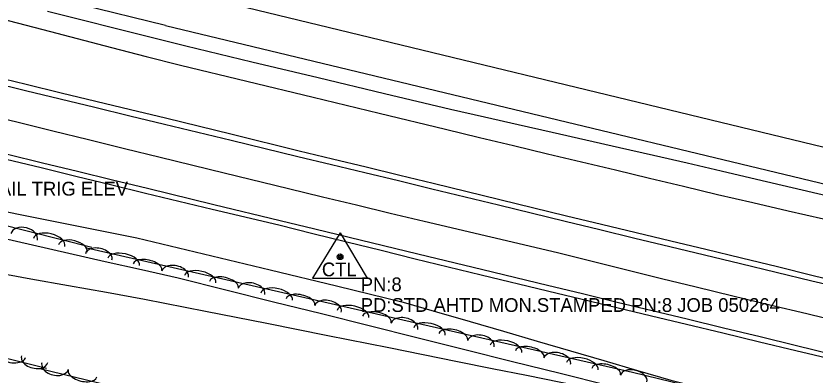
# Model space of a CAD drawing. Extents: x 1441650 to 1491889, y 345904 to 358319.
# Drawn here: x 1449187.5 to 1449477.3, y 353638.8 to 353769 of the extents above; entities that cross this region are included whole.
import ezdxf

# ---------------------------------------------------------------- set-up
doc = ezdxf.new("R2010")
doc.units = 0
for name, color, linetype in [('S_DITCHLINE', 7, 'Continuous'), ('S_EDGE_PAVEMENT', 7, 'Continuous'), ('S_MISC_BOUNDARY', 7, 'Continuous'), ('S_PAVEMENT_CROWN', 7, 'Continuous'), ('S_PRIMARY_CTL', 7, 'Continuous'), ('S_PRIMARY_CTL_ANNOT', 7, 'Continuous'), ('S_SHOULDER', 7, 'Continuous'), ('S_TREE', 7, 'Continuous'), ('S_WATER_UTILITIES', 7, 'Continuous')]:
    doc.layers.add(name, color=color, linetype=linetype)

msp = doc.modelspace()

# ---------------------------------------------------------------- linework, layer by layer
at = {"layer": 'S_DITCHLINE'}
for points in [[(1449172.19, 353770.52), (1449184.69, 353767.29), (1449197.19, 353764.05), (1449209.69, 353760.81), (1449222.18, 353757.57), (1449234.68, 353754.34), (1449247.18, 353751.1), (1449271.2, 353745.31), (1449295.22, 353739.51), (1449319.24, 353733.72), (1449343.26, 353727.93), (1449355.59, 353724.98), (1449367.92, 353722.03), (1449380.26, 353719.07), (1449392.59, 353716.12), (1449404.93, 353713.17), (1449417.26, 353710.22), (1449429.59, 353707.27), (1449441.93, 353704.32), (1449454.72, 353701.35), (1449467.5, 353698.39), (1449480.29, 353695.43)], [(1449198.91, 353770.77), (1449211.45, 353767.61), (1449223.99, 353764.44), (1449236.53, 353761.27), (1449249.07, 353758.1), (1449273.08, 353752.38), (1449297.08, 353746.66), (1449321.09, 353740.94), (1449345.1, 353735.21), (1449357.36, 353732.42), (1449369.62, 353729.64), (1449381.88, 353726.85), (1449394.14, 353724.06), (1449406.4, 353721.27), (1449418.66, 353718.48), (1449430.92, 353715.69), (1449443.18, 353712.9), (1449456.09, 353709.85), (1449468.99, 353706.8), (1449481.9, 353703.75)], [(1449180.57, 353698.72), (1449193.27, 353696.19), (1449205.97, 353693.66), (1449218.67, 353691.13), (1449231.36, 353688.61), (1449255.49, 353682.78), (1449279.62, 353676.95), (1449303.74, 353671.12), (1449327.87, 353665.29), (1449340.01, 353661.75), (1449352.16, 353658.22), (1449364.3, 353654.68), (1449376.45, 353651.14), (1449388.59, 353647.6), (1449400.73, 353644.07), (1449412.88, 353640.53), (1449425.02, 353636.99), (1449437.7, 353633.82), (1449450.38, 353630.64), (1449463.06, 353627.46), (1449475.75, 353624.28), (1449488.43, 353621.11)], [(1449179.07, 353676.19), (1449192.83, 353673.74), (1449206.6, 353671.29), (1449220.36, 353668.84), (1449234.12, 353666.39), (1449256.26, 353661.99), (1449278.41, 353657.6), (1449300.56, 353653.2), (1449322.7, 353648.8), (1449335.18, 353646.28), (1449347.65, 353643.76), (1449360.13, 353641.24), (1449372.61, 353638.73), (1449385.08, 353636.21), (1449397.56, 353633.69), (1449410.03, 353631.17), (1449422.51, 353628.65), (1449435.1, 353625.63), (1449447.69, 353622.61), (1449460.28, 353619.6), (1449472.87, 353616.58), (1449485.46, 353613.56)]]:
    msp.add_lwpolyline(points, dxfattribs=at)
at = {"layer": 'S_EDGE_PAVEMENT'}
for points in [[(1449178.65, 353744.93), (1449190.9, 353741.95), (1449203.51, 353738.91), (1449216.12, 353735.87), (1449228.73, 353732.82), (1449241.34, 353729.78), (1449265.52, 353723.94), (1449289.71, 353718.1), (1449301.87, 353715.17), (1449314.02, 353712.23), (1449326.18, 353709.29), (1449338.33, 353706.36), (1449362.48, 353700.48), (1449386.63, 353694.61), (1449399.27, 353691.54), (1449411.92, 353688.48), (1449424.56, 353685.42), (1449437.21, 353682.36), (1449450.18, 353679.24), (1449463.16, 353676.13), (1449476.14, 353673.02), (1449489.11, 353669.9)], [(1449184.44, 353718.83), (1449197.13, 353715.75), (1449209.83, 353712.67), (1449222.53, 353709.59), (1449235.22, 353706.52), (1449259.28, 353700.68), (1449283.33, 353694.84), (1449295.82, 353691.83), (1449308.31, 353688.82), (1449320.79, 353685.81), (1449333.28, 353682.8), (1449356.78, 353677.11), (1449380.28, 353671.41), (1449392.92, 353668.34), (1449405.56, 353665.28), (1449418.2, 353662.21), (1449430.84, 353659.15), (1449444.09, 353655.94), (1449457.34, 353652.74), (1449470.59, 353649.53), (1449483.84, 353646.32)]]:
    msp.add_lwpolyline(points, dxfattribs=at)
at = {"layer": 'S_MISC_BOUNDARY'}
for points in [[(1449241.67, 353765.51), (1449027.55, 353818.1), (1449019.59, 353823.64), (1449016.14, 353835.92), (1449016.85, 353908.9), (1449017.54, 354002.09)], [(1449241.67, 353765.51), (1449592.66, 353681.24), (1449706.59, 353653.05)]]:
    msp.add_lwpolyline(points, dxfattribs=at)
at = {"layer": 'S_PAVEMENT_CROWN'}
msp.add_lwpolyline([(1449163.78, 353736.34), (1449187.85, 353730.56), (1449200.83, 353727.37), (1449213.81, 353724.18), (1449226.79, 353720.99), (1449239.77, 353717.8), (1449263.05, 353712.13), (1449286.32, 353706.46), (1449298.62, 353703.48), (1449310.92, 353700.51), (1449323.21, 353697.54), (1449335.51, 353694.57), (1449359.72, 353688.91), (1449383.93, 353683.25), (1449396.48, 353680.13), (1449409.03, 353677.01), (1449421.59, 353673.88), (1449434.14, 353670.76), (1449447.51, 353667.54), (1449460.88, 353664.32), (1449474.26, 353661.1), (1449487.63, 353657.88)], dxfattribs=at)
at = {"layer": 'S_PRIMARY_CTL'}
for p, q in [((1449305.01, 353690.4), (1449294.97, 353673.89)), ((1449305.01, 353690.4), (1449314.83, 353673.89)), ((1449294.97, 353673.89), (1449314.83, 353673.89))]:
    msp.add_line(p, q, dxfattribs=at)
for radius in [1.04, 0.609, 0.344]:
    msp.add_circle((1449305.01, 353681.7), radius, dxfattribs=at)
at = {"layer": 'S_SHOULDER'}
for points in [[(1449179.05, 353747.16), (1449191.22, 353744.22), (1449203.83, 353741.17), (1449216.44, 353738.11), (1449229.06, 353735.06), (1449241.67, 353732), (1449265.91, 353726.08), (1449290.14, 353720.15), (1449302.31, 353717.21), (1449314.49, 353714.27), (1449326.66, 353711.33), (1449338.83, 353708.39), (1449362.99, 353702.48), (1449387.15, 353696.56), (1449399.77, 353693.54), (1449412.4, 353690.52), (1449425.03, 353687.49), (1449437.66, 353684.47), (1449450.65, 353681.29), (1449463.64, 353678.12), (1449476.63, 353674.95), (1449489.61, 353671.78)], [(1449183.96, 353717.12), (1449196.58, 353714.03), (1449209.19, 353710.95), (1449221.81, 353707.86), (1449234.43, 353704.78), (1449258.6, 353699), (1449282.78, 353693.22), (1449295.15, 353690.17), (1449307.53, 353687.11), (1449319.9, 353684.05), (1449332.28, 353681), (1449356.24, 353675.17), (1449380.21, 353669.35), (1449392.81, 353666.34), (1449405.41, 353663.33), (1449418, 353660.32), (1449430.6, 353657.31), (1449443.84, 353654.12), (1449457.08, 353650.92), (1449470.33, 353647.73), (1449483.57, 353644.53)]]:
    msp.add_lwpolyline(points, dxfattribs=at)
at = {"layer": 'S_TREE'}
for points in [[(1448164.92, 353940.81), (1448249.39, 353922.57), (1448359.07, 353895.66), (1448463.63, 353870.23), (1448540.52, 353850.86), (1448562.98, 353841.37), (1448593.01, 353834.89), (1448633.64, 353826.11), (1448718.7, 353807.44), (1448803.64, 353789.1), (1448863.56, 353775.84), (1448904.08, 353761.08), (1448983.58, 353741.29), (1449050.52, 353726.63), (1449135.46, 353705.27), (1449214.98, 353685.13)], [(1449198.55, 353641.16), (1448994.76, 353691.9), (1448844.41, 353728.56), (1448750.54, 353748.91), (1448674.24, 353769.2), (1448614.45, 353786.08), (1448584.4, 353793.37), (1448535.16, 353804.01), (1448460.45, 353823.73), (1448403.66, 353837.92), (1448355.16, 353848.39), (1448265.33, 353872.32), (1448229.62, 353880.04), (1448194.99, 353887.51), (1448124.02, 353906.49)], [(1449180.23, 353689.02), (1449193.44, 353686.02), (1449206.64, 353683.03), (1449219.85, 353680.04), (1449233.05, 353677.04), (1449246.26, 353674.05), (1449263.58, 353669.73), (1449280.91, 353665.41), (1449298.23, 353661.08), (1449315.56, 353656.76), (1449332.88, 353652.44), (1449350.21, 353648.12), (1449367.53, 353643.79), (1449384.86, 353639.47), (1449402.18, 353635.15), (1449419.5, 353630.83), (1449436.83, 353626.51), (1449454.15, 353622.18), (1449471.48, 353617.86), (1449488.8, 353613.54)], [(1449180.23, 353689.02), (1449193.44, 353686.02), (1449206.64, 353683.03), (1449219.85, 353680.04), (1449233.05, 353677.04), (1449246.26, 353674.05), (1449263.58, 353669.73), (1449280.91, 353665.41), (1449298.23, 353661.08), (1449315.56, 353656.76), (1449332.88, 353652.44), (1449350.21, 353648.12), (1449367.53, 353643.79), (1449384.86, 353639.47), (1449402.18, 353635.15), (1449419.5, 353630.83), (1449436.83, 353626.51), (1449454.15, 353622.18), (1449471.48, 353617.86), (1449488.8, 353613.54)], [(1449213.13, 353684.9), (1449411.1, 353639.85), (1449617.01, 353589.74), (1449776.7, 353552.52), (1449875.91, 353528.95), (1449975.69, 353504.38), (1450069.22, 353479.4), (1450132.33, 353465.04), (1450208.47, 353444.79), (1450290.51, 353426)], [(1450255.84, 353384.72), (1450088.93, 353426.41), (1449953.23, 353459.15), (1449860.73, 353480.2), (1449779.88, 353502.2), (1449716.43, 353516.64), (1449650.08, 353534.03), (1449589.19, 353547.88), (1449507.99, 353568.19), (1449451.14, 353581.22), (1449383.19, 353596.68), (1449301.22, 353615.58), (1449196.09, 353641.05)]]:
    msp.add_lwpolyline(points, dxfattribs=at)
for centre, major_axis, ratio, start_param, end_param in [((1449190.47, 353688.88), (-4.8, 1.22), 0.68531, 3.141593, 6.283185), ((1449199.51, 353686.86), (-5.69, 1.44), 0.550079, 3.141593, 6.283185), ((1449208.11, 353684.69), (-5.18, 1.31), 0.540699, 3.141593, 6.283185), ((1449217.48, 353681.7), (-4.83, 1.1), 0.619831, 3.141466, 6.283059), ((1449226.56, 353679.88), (-5.72, 1.3), 0.497521, 3.14151, 6.283102), ((1449235.21, 353677.91), (-5.21, 1.19), 0.489037, 3.141512, 6.283105), ((1449245.2, 353675.39), (-4.83, 1.1), 0.619831, 3.141466, 6.283059), ((1449254.28, 353673.57), (-5.72, 1.3), 0.497521, 3.14151, 6.283102), ((1449262.93, 353671.6), (-5.21, 1.19), 0.489037, 3.141512, 6.283105), ((1449272.92, 353669.08), (-4.83, 1.1), 0.619831, 3.141466, 6.283059), ((1449282, 353667.26), (-5.72, 1.3), 0.497521, 3.14151, 6.283102), ((1449290.65, 353665.29), (-5.21, 1.19), 0.489037, 3.141512, 6.283105), ((1449300.64, 353662.77), (-4.83, 1.1), 0.619831, 3.141466, 6.283059), ((1449309.72, 353660.95), (-5.72, 1.3), 0.497521, 3.14151, 6.283102), ((1449318.37, 353658.98), (-5.21, 1.19), 0.489037, 3.141512, 6.283105), ((1449328.36, 353656.47), (-4.83, 1.1), 0.619831, 3.141466, 6.283059), ((1449337.44, 353654.64), (-5.72, 1.3), 0.497521, 3.14151, 6.283102), ((1449346.09, 353652.67), (-5.21, 1.19), 0.489037, 3.141512, 6.283105), ((1449356.08, 353650.16), (-4.83, 1.1), 0.619831, 3.141466, 6.283059), ((1449365.16, 353648.33), (-5.72, 1.3), 0.497521, 3.14151, 6.283102), ((1449373.8, 353646.37), (-5.21, 1.19), 0.489037, 3.141512, 6.283105), ((1449185.25, 353646.57), (5.69, -1.42), 0.52958, 3.141669, 6.283262), ((1449194.29, 353644.58), (4.81, -1.2), 0.659771, 3.141714, 6.283307), ((1449383.8, 353643.85), (-4.83, 1.1), 0.619831, 3.141466, 6.283059), ((1449392.88, 353642.02), (-5.72, 1.3), 0.497521, 3.14151, 6.283102), ((1449201.69, 353642.14), (4.82, -1.17), 0.68337, 3.14162, 6.283213), ((1449401.52, 353640.06), (-5.21, 1.19), 0.489037, 3.141512, 6.283105), ((1449211.64, 353639.46), (5.2, -1.26), 0.539168, 3.141609, 6.283202), ((1449411.5, 353637.53), (-4.81, 1.2), 0.619869, 3.150107, 6.291699)]:
    msp.add_ellipse(centre, major_axis=major_axis, ratio=ratio, start_param=start_param, end_param=end_param, dxfattribs=at)
at = {"layer": 'S_WATER_UTILITIES'}
msp.add_line((1448988.85, 353840.47), (1450406.03, 353497.36), dxfattribs=at)

# ---------------------------------------------------------------- texts
at = {"layer": 'S_PRIMARY_CTL'}
msp.add_text('CTL', height=5, rotation=360, dxfattribs=at).set_placement((1449298.42, 353674.62))
at = {"layer": 'S_PRIMARY_CTL_ANNOT'}
for s, p in [('PD:SET 8" NAIL TRIG ELEV', (1449142.52, 353703.87)), ('PN:8', (1449312.51, 353669.2)), ('PD:STD AHTD MON.STAMPED PN:8 JOB 050264', (1449312.51, 353661.7))]:
    msp.add_text(s, height=5, dxfattribs=at).set_placement(p)

doc.saveas('drawing.dxf')
